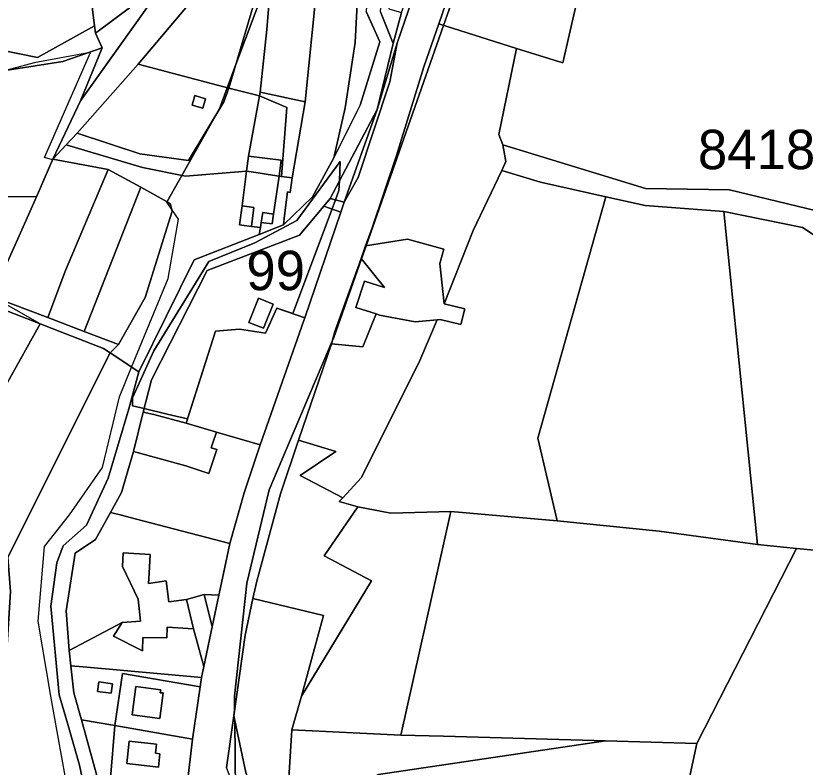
# Model space of a CAD drawing. Extents: x -477304 to -465429, y -1159113 to -1149210.
# Drawn here: x -475584.5 to -475284.1, y -1153027 to -1152741 of the extents above; entities that cross this region are included whole.
import ezdxf

# ---------------------------------------------------------------- set-up
doc = ezdxf.new("R2010")
doc.units = 0
for name, color, linetype in [('BPEJ_s', 7, 'Continuous'), ('orna_s', 7, 'Continuous'), ('ostatni_s', 7, 'Continuous'), ('PUPFL_s', 7, 'Continuous'), ('trav_porost_s', 7, 'Continuous'), ('voda_s', 7, 'Continuous'), ('zahrada_s', 7, 'Continuous')]:
    doc.layers.add(name, color=color, linetype=linetype)

msp = doc.modelspace()

# ---------------------------------------------------------------- linework, layer by layer
at = {"layer": 'BPEJ_s'}
for points in [[(-475500.81, -1153036.32), (-475501.16, -1153009.29), (-475501.54, -1153007.49), (-475501.21, -1153005.16), (-475501.28, -1153000), (-475496.5, -1152957), (-475488, -1152921.5), (-475464.1, -1152864.93), (-475463.5, -1152863.5), (-475452.96, -1152833.54), (-475451.22, -1152828.6), (-475421.69, -1152744.68), (-475407.14, -1152703.33)], [(-475407.14, -1152703.33), (-475421.69, -1152744.68), (-475451.22, -1152828.6), (-475452.96, -1152833.54), (-475463.5, -1152863.5), (-475464.1, -1152864.93), (-475488, -1152921.5), (-475496.5, -1152957), (-475501.28, -1153000), (-475501.21, -1153005.16)], [(-475489.77, -1152730.19), (-475500.69, -1152759.54), (-475504, -1152768.43), (-475507, -1152776.5), (-475507.3, -1152777.03), (-475521.24, -1152801.78), (-475526.88, -1152811.78), (-475527, -1152812), (-475525.07, -1152814.79), (-475524.91, -1152815.39), (-475535.25, -1152848.29), (-475545.44, -1152866.11), (-475548.51, -1152869.36), (-475587.54, -1152947.04)], [(-475563.53, -1153042.27), (-475569, -1153012), (-475571.07, -1153000), (-475576, -1152971.5), (-475573.5, -1152943), (-475564, -1152931), (-475551.5, -1152913), (-475545, -1152886), (-475540.37, -1152874.73), (-475526.5, -1152841), (-475522.5, -1152818.5), (-475525.07, -1152814.79), (-475527, -1152812), (-475526.88, -1152811.78), (-475521.24, -1152801.78), (-475507.3, -1152777.03), (-475507, -1152776.5), (-475504, -1152768.43), (-475500.69, -1152759.54), (-475489.77, -1152730.19)], [(-475619.33, -1152937.28), (-475575.21, -1152858.31), (-475593.59, -1152847.84), (-475576.52, -1152809.97), (-475570.52, -1152795.86), (-475573.5, -1152795), (-475556, -1152755), (-475557.53, -1152755.29), (-475577.5, -1152759), (-475587.33, -1152761.64)], [(-475619.33, -1152937.28), (-475575.21, -1152858.31), (-475593.59, -1152847.84), (-475576.52, -1152809.97), (-475570.52, -1152795.86), (-475573.5, -1152795), (-475556, -1152755), (-475557.53, -1152755.29), (-475577.5, -1152759), (-475587.33, -1152761.64)], [(-475524.91, -1152815.39), (-475535.25, -1152848.29), (-475545.44, -1152866.11), (-475548.51, -1152869.36), (-475587.54, -1152947.04)], [(-475563.53, -1153042.27), (-475569, -1153012), (-475571.07, -1153000), (-475576, -1152971.5), (-475573.5, -1152943), (-475564, -1152931), (-475551.5, -1152913), (-475545, -1152886), (-475540.37, -1152874.73), (-475526.5, -1152841), (-475522.5, -1152818.5), (-475525.07, -1152814.79), (-475524.91, -1152815.39)], [(-475268.28, -1152945.55), (-475287.45, -1152943.72), (-475325.37, -1153017.96), (-475330.61, -1153042.24)], [(-475268.28, -1152945.55), (-475287.45, -1152943.72), (-475325.37, -1153017.96), (-475330.61, -1153042.24)], [(-475501.21, -1153005.16), (-475501.54, -1153007.49), (-475501.16, -1153009.29), (-475500.81, -1153036.32)]]:
    msp.add_lwpolyline(points, dxfattribs=at)
for points in [[(-475464.14, -1152814.54), (-475479.09, -1152854.4), (-475485.14, -1152852.33), (-475489.52, -1152861.83), (-475499.35, -1152860.35), (-475508.44, -1152861.13), (-475519.11, -1152894.42), (-475526.82, -1152892.6), (-475535.6, -1152890.53), (-475540, -1152889.5), (-475540, -1152886.5), (-475532, -1152868.5), (-475511, -1152834.5), (-475493.5, -1152827.5), (-475477.5, -1152819), (-475461, -1152796.5), (-475461.34, -1152803.9), (-475461.5, -1152807.5), (-475462.83, -1152811.05)], [(-475464.14, -1152814.54), (-475462.83, -1152811.05), (-475461.5, -1152807.5), (-475461.34, -1152803.9), (-475461, -1152796.5), (-475477.5, -1152819), (-475493.5, -1152827.5), (-475511, -1152834.5), (-475532, -1152868.5), (-475540, -1152886.5), (-475540, -1152889.5), (-475535.6, -1152890.53), (-475526.82, -1152892.6), (-475519.11, -1152894.42), (-475508.44, -1152861.13), (-475499.35, -1152860.35), (-475489.52, -1152861.83), (-475485.14, -1152852.33), (-475479.09, -1152854.4)]]:
    msp.add_lwpolyline(points, close=True, dxfattribs=at)
at = {"layer": 'orna_s'}
for points in [[(-475474.41, -1152773.74), (-475470.29, -1152733.49), (-475466.26, -1152707.82), (-475459.33, -1152709.97), (-475453.25, -1152709.43), (-475455.35, -1152751.18), (-475459.14, -1152776.1), (-475463.5, -1152795.08), (-475471.52, -1152809.95), (-475482.63, -1152820.63), (-475482.23, -1152817.05), (-475481.05, -1152808.1), (-475480.01, -1152808.24), (-475479.28, -1152802.69)], [(-475492.49, -1152731.72), (-475503.36, -1152768.6), (-475537.87, -1152759.39), (-475508.67, -1152724.8), (-475503.55, -1152727.41)], [(-475488.91, -1152746.29), (-475487.74, -1152730.6), (-475483.62, -1152731.43), (-475470.29, -1152733.49), (-475474.41, -1152773.74), (-475491.45, -1152770.14)], [(-475537.87, -1152759.39), (-475503.36, -1152768.6), (-475505.33, -1152773.76), (-475518.78, -1152796.1), (-475537.26, -1152793.53), (-475561.15, -1152785.65)], [(-475516.28, -1152771.43), (-475517.38, -1152775.02), (-475513.35, -1152776.25), (-475512.25, -1152772.66)], [(-475593.59, -1152847.84), (-475576.52, -1152809.97), (-475570.41, -1152795.61), (-475549.31, -1152799.53), (-475565.52, -1152837.98), (-475572.32, -1152855.91)]]:
    msp.add_lwpolyline(points, close=True, dxfattribs=at)
at = {"layer": 'ostatni_s'}
for points in [[(-475528.22, -1152728.96), (-475516.03, -1152717.12), (-475516.8, -1152709.11), (-475525.94, -1152703.82), (-475549.78, -1152702.51), (-475561.12, -1152693.94), (-475574.39, -1152690.12), (-475584.04, -1152671.96), (-475547.68, -1152668.96), (-475550.48, -1152681.26), (-475495.82, -1152689.6), (-475490.4, -1152697.4), (-475498.36, -1152710.25), (-475510.93, -1152722.23), (-475508.67, -1152724.8), (-475537.87, -1152759.39), (-475561.15, -1152785.65), (-475565.28, -1152790.1), (-475570.41, -1152795.61), (-475559.87, -1152773.35)], [(-475429.06, -1152720.89), (-475430.92, -1152726.59), (-475439.34, -1152751.52), (-475447.03, -1152776.68), (-475440.93, -1152751.63), (-475437.73, -1152739.75), (-475430.58, -1152719.98)], [(-475454.24, -1152802.53), (-475459.54, -1152811.92), (-475447.03, -1152776.68), (-475439.34, -1152751.52), (-475442.11, -1152766.19)], [(-475513.35, -1152776.25), (-475517.38, -1152775.02), (-475516.28, -1152771.43), (-475512.25, -1152772.66)], [(-475464.82, -1152810.53), (-475447.03, -1152776.68), (-475459.54, -1152811.92)], [(-475486.38, -1152816.51), (-475490.52, -1152815.96), (-475491.06, -1152819.68), (-475491.35, -1152821.65), (-475494.81, -1152821.19), (-475493.89, -1152813.96), (-475498.35, -1152813.37), (-475496.67, -1152800.17), (-475492.21, -1152800.76), (-475488.39, -1152801.5), (-475484.25, -1152802.04)], [(-475483.43, -1152802.15), (-475479.28, -1152802.69), (-475480.01, -1152808.24), (-475481.05, -1152808.1), (-475482.23, -1152817.05), (-475482.63, -1152820.63), (-475491.87, -1152824.25), (-475491.35, -1152821.65), (-475491.06, -1152819.68), (-475486.87, -1152820.23), (-475486.38, -1152816.51), (-475484.25, -1152802.04)], [(-475464.82, -1152810.53), (-475459.54, -1152811.92), (-475460.83, -1152815.72), (-475467.24, -1152813.44)], [(-475499.35, -1152860.35), (-475508.44, -1152861.13), (-475519.66, -1152896.13), (-475531.89, -1152892.84), (-475535.95, -1152891.92), (-475532.87, -1152879.56), (-475511.67, -1152838.03), (-475476.52, -1152824.58), (-475467.24, -1152813.44), (-475460.83, -1152815.72), (-475474.51, -1152855.97), (-475485.14, -1152852.33), (-475489.52, -1152861.83)], [(-475499.35, -1152820.59), (-475498.35, -1152813.37), (-475493.89, -1152813.96), (-475494.81, -1152821.19)], [(-475490.52, -1152815.96), (-475486.38, -1152816.51), (-475486.87, -1152820.23), (-475491.06, -1152819.68)], [(-475435.38, -1152826.04), (-475421.65, -1152829.81), (-475423.16, -1152835.29), (-475421.55, -1152850.68), (-475413.67, -1152852.57), (-475415.09, -1152858.5), (-475422.97, -1152856.61), (-475424.14, -1152856.73), (-475432.48, -1152857.55), (-475446.06, -1152854.94), (-475447.4, -1152854.49), (-475455.03, -1152852.06), (-475451.82, -1152842.06), (-475444.2, -1152844.51), (-475453.09, -1152833.38), (-475451.39, -1152828.63)], [(-475490.22, -1152859.94), (-475486.59, -1152850.73), (-475492.17, -1152848.53), (-475495.8, -1152857.74)], [(-475486.59, -1152850.73), (-475490.22, -1152859.94), (-475495.8, -1152857.74), (-475492.17, -1152848.53)], [(-475509.64, -1152903.9), (-475510.15, -1152905.42), (-475507.97, -1152906.15), (-475511.03, -1152915.25), (-475519.75, -1152912.32), (-475539.67, -1152906.85), (-475535.95, -1152891.92), (-475531.89, -1152892.84), (-475519.66, -1152896.13), (-475508.15, -1152899.46)], [(-475533.29, -1152946.04), (-475543.57, -1152945.42), (-475543.89, -1152950.61), (-475537.86, -1152963.03), (-475537.03, -1152971.49), (-475544.04, -1152971.94), (-475564.12, -1152982.64), (-475565.3, -1152967.49), (-475561.8, -1152945.58), (-475554.15, -1152940.37), (-475548.43, -1152930.05), (-475544.24, -1152931.13), (-475538.99, -1152932.46), (-475503.01, -1152941.9), (-475505.46, -1152953.31), (-475507.18, -1152961.51), (-475512.75, -1152961.31), (-475519.5, -1152963.16), (-475526.22, -1152964.09), (-475527.23, -1152956.14), (-475533.95, -1152957.07), (-475533.72, -1152953.13)], [(-475533.95, -1152957.07), (-475527.23, -1152956.14), (-475526.22, -1152964.09), (-475519.5, -1152963.16), (-475516.91, -1152974.32), (-475526.88, -1152973.78), (-475526.96, -1152977.78), (-475536.06, -1152977.6), (-475536.23, -1152982.69), (-475547.34, -1152977.21), (-475544.04, -1152971.94), (-475537.03, -1152971.49), (-475537.86, -1152963.03), (-475543.89, -1152950.61), (-475543.57, -1152945.42), (-475533.29, -1152946.04), (-475533.72, -1152953.13)], [(-475516.91, -1152974.32), (-475519.5, -1152963.16), (-475512.75, -1152961.31), (-475509.71, -1152973.57), (-475512.88, -1152988.66)], [(-475546.78, -1153011.14), (-475543.84, -1152991.36), (-475514.34, -1152996.46), (-475517.23, -1153016.33)], [(-475553.36, -1152998.26), (-475552.92, -1152994.58), (-475547.7, -1152995.24), (-475548.15, -1152998.9)], [(-475538.76, -1152996.3), (-475540.14, -1153007.12), (-475529.68, -1153008.45), (-475528.44, -1152998.75), (-475529.47, -1152998.7), (-475529.32, -1152997.51)], [(-475529.47, -1152998.7), (-475528.44, -1152998.75), (-475529.68, -1153008.45), (-475540.14, -1153007.12), (-475538.76, -1152996.3), (-475529.32, -1152997.51)], [(-475471.51, -1153122.26), (-475483.51, -1153143.2), (-475484.05, -1153148.63), (-475463.25, -1153144.42), (-475478.77, -1153148.77), (-475489.43, -1153151.64), (-475491.02, -1153144.27), (-475478.7, -1153120.92), (-475475.62, -1153106.62), (-475482.9, -1153085.35), (-475494.64, -1153052.66), (-475504.3, -1153027.08), (-475501.54, -1153007.49), (-475496.95, -1153029.07), (-475472.52, -1153095.04), (-475474.55, -1153095.68), (-475469.57, -1153111.41)], [(-475546.78, -1153011.14), (-475517.23, -1153016.33), (-475519.45, -1153035.84), (-475548.45, -1153031.15)], [(-475530.21, -1153026.97), (-475529.67, -1153021.91), (-475531.35, -1153021.73), (-475530.98, -1153018.27), (-475541.35, -1153017.16), (-475542.27, -1153025.67)], [(-475530.21, -1153026.97), (-475542.27, -1153025.67), (-475541.35, -1153017.16), (-475530.98, -1153018.27), (-475531.35, -1153021.73), (-475529.67, -1153021.91)]]:
    msp.add_lwpolyline(points, close=True, dxfattribs=at)
for points in [[(-475412.15, -1152710.92), (-475423.54, -1152744.1), (-475429.17, -1152760.48), (-475439.62, -1152794.25), (-475448.91, -1152821.68), (-475451.39, -1152828.63), (-475453.09, -1152833.38), (-475463.02, -1152861.18), (-475464.37, -1152865.85), (-475476.85, -1152902.59), (-475483.8, -1152923.03), (-475492.8, -1152956.23), (-475494.22, -1152962.84), (-475497.2, -1152976.78), (-475501.54, -1153007.49), (-475504.3, -1153027.08)], [(-475510.82, -1153134.41), (-475513.74, -1153112.64), (-475517.49, -1153089), (-475520.57, -1153045.64), (-475519.45, -1153035.84), (-475517.23, -1153016.33), (-475514.34, -1152996.46), (-475513.77, -1152992.91), (-475512.88, -1152988.66), (-475509.71, -1152973.57), (-475507.18, -1152961.51), (-475505.46, -1152953.31), (-475503.01, -1152941.9), (-475497.54, -1152922.65), (-475491.51, -1152904.28), (-475474.88, -1152857.07), (-475474.51, -1152855.97), (-475460.83, -1152815.72), (-475459.54, -1152811.92), (-475454.24, -1152802.53), (-475442.11, -1152766.19), (-475439.34, -1152751.52), (-475430.92, -1152726.59)], [(-475593.59, -1152847.84), (-475572.32, -1152855.91), (-475558.47, -1152861.17), (-475545.44, -1152866.11), (-475535.25, -1152848.29), (-475524.91, -1152815.39), (-475525.7, -1152812.42), (-475536.93, -1152806.29), (-475549.31, -1152799.53), (-475570.41, -1152795.61), (-475565.28, -1152790.1), (-475536.3, -1152798.75), (-475519.91, -1152802.05), (-475496.67, -1152800.17), (-475498.35, -1152813.37), (-475499.35, -1152820.59), (-475494.81, -1152821.19), (-475491.35, -1152821.65), (-475491.87, -1152824.25), (-475516.59, -1152833.94), (-475537.64, -1152876.53), (-475548.51, -1152869.36), (-475551.06, -1152867.68), (-475575.21, -1152858.31), (-475594.83, -1152850.7)]]:
    msp.add_lwpolyline(points, dxfattribs=at)
at = {"layer": 'PUPFL_s'}
for points in [[(-475688.75, -1152784.73), (-475693.19, -1152770.91), (-475686.56, -1152768.49), (-475621.57, -1152758.65), (-475624.23, -1152747.16), (-475576.16, -1152756.87), (-475554.46, -1152744.91), (-475554.12, -1152747.68), (-475551.6, -1152753.22), (-475566.51, -1152758.41), (-475598.28, -1152763.34), (-475604.67, -1152767.58), (-475593.82, -1152785.42), (-475688.69, -1152799.79)], [(-475694.55, -1152800.67), (-475688.69, -1152799.79), (-475593.82, -1152785.42), (-475604.67, -1152767.58), (-475598.28, -1152763.34), (-475566.51, -1152758.41), (-475551.6, -1152753.22), (-475559.87, -1152773.35), (-475570.41, -1152795.61), (-475576.52, -1152809.97), (-475644.5, -1152809.53), (-475700.83, -1152807.76), (-475694.32, -1152806.09)], [(-475154.57, -1152960.71), (-475188.25, -1153073.92), (-475205.9, -1153072.04), (-475319.2, -1153107.9), (-475350.51, -1153121.3), (-475347.24, -1153109.36), (-475336.52, -1153070.18), (-475330.61, -1153042.24), (-475325.37, -1153017.96), (-475287.45, -1152943.72), (-475268.28, -1152945.55), (-475240.48, -1152947.68), (-475185.82, -1152950.28), (-475184.7, -1152902.6), (-475190.97, -1152854.13), (-475193.07, -1152845.82), (-475161.18, -1152813.24), (-475126.45, -1152850.38), (-475138.02, -1152881.46), (-475143.48, -1152923), (-475153.28, -1152956.92)], [(-475575.21, -1152858.31), (-475619.33, -1152937.28), (-475611.96, -1152940.26), (-475621.62, -1152973.88), (-475613.73, -1152977.13), (-475617.49, -1153013.79), (-475630.92, -1152974.27), (-475631.11, -1153024.55), (-475648.02, -1153026.57), (-475643.82, -1153008.41), (-475642.55, -1152978.65), (-475635.17, -1152947.89), (-475627.73, -1152930.46), (-475594.83, -1152850.7)]]:
    msp.add_lwpolyline(points, close=True, dxfattribs=at)
for points in [[(-475743.28, -1152815.41), (-475700.83, -1152807.76), (-475644.5, -1152809.53), (-475576.52, -1152809.97), (-475593.59, -1152847.84), (-475594.83, -1152850.7), (-475627.73, -1152930.46), (-475635.17, -1152947.89), (-475642.55, -1152978.65), (-475643.82, -1153008.41), (-475648.02, -1153026.57), (-475631.11, -1153024.55), (-475635.36, -1153085.02), (-475662.21, -1153095.67), (-475701.5, -1153108.22), (-475770.43, -1153174.06)], [(-475635.36, -1153085.02), (-475631.11, -1153024.55), (-475630.92, -1152974.27), (-475617.49, -1153013.79), (-475590.2, -1153019.39), (-475586.48, -1152960.09), (-475587.54, -1152947.04), (-475548.51, -1152869.36), (-475537.64, -1152876.53), (-475541.47, -1152890.66), (-475549.36, -1152917.02), (-475557.61, -1152934.96), (-475566.47, -1152942.81), (-475568.81, -1152949.28), (-475571.1, -1152965.73), (-475567.92, -1152999.53), (-475564.76, -1153010.23), (-475560.24, -1153026.23), (-475557.79, -1153037.72)]]:
    msp.add_lwpolyline(points, dxfattribs=at)
at = {"layer": 'trav_porost_s'}
for points in [[(-475563.59, -1152714.27), (-475556.79, -1152726.11), (-475554.46, -1152744.91), (-475576.16, -1152756.87), (-475624.23, -1152747.16), (-475621.57, -1152758.65), (-475686.56, -1152768.49), (-475695.79, -1152741.11), (-475675.66, -1152712.58), (-475642.36, -1152708.05), (-475639.99, -1152696.96), (-475614.53, -1152691.15), (-475585.75, -1152697.58), (-475579.41, -1152701.49), (-475568.62, -1152709.29)], [(-475556.79, -1152726.11), (-475563.59, -1152714.27), (-475568.62, -1152709.29), (-475579.41, -1152701.49), (-475574.39, -1152690.12), (-475561.12, -1152693.94), (-475549.78, -1152702.51), (-475547.62, -1152704.31), (-475539.13, -1152723.9), (-475540.16, -1152737.25), (-475554.12, -1152747.68), (-475554.46, -1152744.91)], [(-475554.12, -1152747.68), (-475540.16, -1152737.25), (-475539.13, -1152723.9), (-475547.62, -1152704.31), (-475549.78, -1152702.51), (-475525.94, -1152703.82), (-475516.8, -1152709.11), (-475516.03, -1152717.12), (-475528.22, -1152728.96), (-475559.87, -1152773.35), (-475551.6, -1152753.22)], [(-475393.95, -1152753.43), (-475423.54, -1152744.1), (-475412.15, -1152710.92), (-475408.98, -1152702.9), (-475391.14, -1152707.11), (-475386.32, -1152711.18), (-475378.53, -1152710.47), (-475366.01, -1152713.43), (-475376.34, -1152758.98)], [(-475451.16, -1152739.41), (-475446.01, -1152751.01), (-475453.49, -1152775), (-475463.5, -1152795.08), (-475459.14, -1152776.1), (-475455.35, -1152751.18), (-475453.25, -1152709.43), (-475449.1, -1152710.68)], [(-475279.36, -1152735.39), (-475267.5, -1152741.66), (-475238.97, -1152771.86), (-475246.77, -1152833.38), (-475279.83, -1152815.27), (-475312.9, -1152807.3), (-475344.92, -1152806.82), (-475399.13, -1152790.1), (-475400.75, -1152786.24), (-475393.95, -1152753.43), (-475376.34, -1152758.98), (-475366.01, -1152713.43), (-475311.18, -1152726.4), (-475305.99, -1152727.63)], [(-475492.49, -1152731.72), (-475503.55, -1152727.41), (-475487.74, -1152730.6), (-475488.91, -1152746.29), (-475491.45, -1152770.14), (-475491.69, -1152771.47), (-475503.36, -1152768.6)], [(-475400.75, -1152786.24), (-475399.13, -1152790.1), (-475397.98, -1152796.54), (-475399.54, -1152799.89), (-475410.48, -1152822.74), (-475421.55, -1152850.68), (-475423.16, -1152835.29), (-475421.65, -1152829.81), (-475435.38, -1152826.04), (-475451.39, -1152828.63), (-475448.91, -1152821.68), (-475439.62, -1152794.25), (-475429.17, -1152760.48), (-475423.54, -1152744.1), (-475393.95, -1152753.43)], [(-475519.91, -1152802.05), (-475536.3, -1152798.75), (-475565.28, -1152790.1), (-475561.15, -1152785.65), (-475537.26, -1152793.53), (-475518.78, -1152796.1), (-475505.33, -1152773.76), (-475503.36, -1152768.6), (-475491.69, -1152771.47), (-475495.93, -1152794.52), (-475496.67, -1152800.17)], [(-475491.45, -1152770.14), (-475474.41, -1152773.74), (-475479.28, -1152802.69), (-475483.43, -1152802.15), (-475481.32, -1152775.88), (-475491.69, -1152771.47)], [(-475495.93, -1152794.52), (-475491.69, -1152771.47), (-475481.32, -1152775.88), (-475483.43, -1152802.15), (-475484.25, -1152802.04), (-475483.45, -1152795.99)], [(-475384.78, -1152804.32), (-475399.54, -1152799.89), (-475397.98, -1152796.54), (-475399.13, -1152790.1), (-475344.92, -1152806.82), (-475312.9, -1152807.3), (-475279.83, -1152815.27), (-475246.77, -1152833.38), (-475201.18, -1152853.32), (-475240.42, -1152843.05), (-475262.43, -1152836.75), (-475285.2, -1152821.61), (-475315.16, -1152815.54), (-475345, -1152813.24), (-475359.94, -1152810)], [(-475484.25, -1152802.04), (-475488.39, -1152801.5), (-475492.21, -1152800.76), (-475496.67, -1152800.17), (-475495.93, -1152794.52), (-475483.45, -1152795.99)], [(-475558.47, -1152861.17), (-475572.32, -1152855.91), (-475565.52, -1152837.98), (-475549.31, -1152799.53), (-475536.93, -1152806.29)], [(-475460.02, -1152924.47), (-475452.88, -1152916.76), (-475430.76, -1152872.18), (-475424.14, -1152856.73), (-475422.97, -1152856.61), (-475415.09, -1152858.5), (-475413.67, -1152852.57), (-475421.55, -1152850.68), (-475410.48, -1152822.74), (-475399.54, -1152799.89), (-475384.78, -1152804.32), (-475359.94, -1152810), (-475385.91, -1152901.78), (-475378.54, -1152933.24), (-475418.96, -1152929.67), (-475441.84, -1152930.38), (-475454.37, -1152927.96), (-475461.39, -1152925.95)], [(-475525.7, -1152812.42), (-475524.91, -1152815.39), (-475535.25, -1152848.29), (-475545.44, -1152866.11), (-475558.47, -1152861.17), (-475536.93, -1152806.29)], [(-475385.91, -1152901.78), (-475359.94, -1152810), (-475345, -1152813.24), (-475315.16, -1152815.54), (-475302.24, -1152942.31), (-475339.72, -1152937.13), (-475378.54, -1152933.24)], [(-475268.28, -1152945.55), (-475287.45, -1152943.72), (-475302.24, -1152942.31), (-475315.16, -1152815.54), (-475285.2, -1152821.61), (-475262.43, -1152836.75), (-475240.42, -1152843.05), (-475244.73, -1152856.39), (-475221.7, -1152869.94), (-475234.99, -1152909.87), (-475240.48, -1152947.68)], [(-475485.14, -1152852.33), (-475474.51, -1152855.97), (-475474.88, -1152857.07), (-475491.51, -1152904.28), (-475508.15, -1152899.46), (-475519.66, -1152896.13), (-475508.44, -1152861.13), (-475499.35, -1152860.35), (-475489.52, -1152861.83)], [(-475548.51, -1152869.36), (-475587.54, -1152947.04), (-475586.48, -1152960.09), (-475590.2, -1153019.39), (-475617.49, -1153013.79), (-475613.73, -1152977.13), (-475621.62, -1152973.88), (-475611.96, -1152940.26), (-475619.33, -1152937.28), (-475575.21, -1152858.31), (-475551.06, -1152867.68)], [(-475483.8, -1152923.03), (-475476.85, -1152902.59), (-475462.75, -1152906.9), (-475476.32, -1152916.03), (-475460.02, -1152924.47), (-475461.39, -1152925.95), (-475454.37, -1152927.96), (-475467.1, -1152946.61), (-475449.11, -1152956.13), (-475475.8, -1153000), (-475467.4, -1152969.33), (-475494.22, -1152962.84), (-475492.8, -1152956.23)], [(-475449.11, -1152956.13), (-475467.1, -1152946.61), (-475454.37, -1152927.96), (-475441.84, -1152930.38), (-475418.96, -1152929.67), (-475437.91, -1153014.81), (-475479.39, -1153012.83), (-475475.8, -1153000)], [(-475302.24, -1152942.31), (-475287.45, -1152943.72), (-475325.37, -1153017.96), (-475360.14, -1153016.97), (-475421.68, -1153015.23), (-475437.91, -1153014.81), (-475418.96, -1152929.67), (-475378.54, -1152933.24), (-475339.72, -1152937.13)], [(-475512.75, -1152961.31), (-475507.18, -1152961.51), (-475509.71, -1152973.57)], [(-475494.22, -1152962.84), (-475467.4, -1152969.33), (-475475.8, -1153000), (-475479.39, -1153012.83), (-475481.6, -1153047.42), (-475463.12, -1153092.06), (-475466.61, -1153093.16), (-475472.52, -1153095.04), (-475496.95, -1153029.07), (-475501.54, -1153007.49), (-475497.2, -1152976.78)], [(-475526.88, -1152973.78), (-475516.91, -1152974.32), (-475512.88, -1152988.66), (-475513.77, -1152992.91), (-475558.81, -1152988.85), (-475563.49, -1152988.42), (-475564.12, -1152982.64), (-475544.04, -1152971.94), (-475547.34, -1152977.21), (-475536.23, -1152982.69), (-475536.06, -1152977.6), (-475526.96, -1152977.78)], [(-475563.49, -1152988.42), (-475558.81, -1152988.85), (-475513.77, -1152992.91), (-475514.34, -1152996.46), (-475543.84, -1152991.36), (-475546.78, -1153011.14), (-475559.5, -1153009.05), (-475562.37, -1152998.73)], [(-475553.36, -1152998.26), (-475548.15, -1152998.9), (-475547.7, -1152995.24), (-475552.92, -1152994.58)], [(-475559.5, -1153009.05), (-475546.78, -1153011.14), (-475548.45, -1153031.15), (-475553.48, -1153030.67)], [(-475437.91, -1153014.81), (-475421.68, -1153015.23), (-475360.14, -1153016.97), (-475446.53, -1153029.81), (-475481.6, -1153047.42), (-475479.39, -1153012.83)], [(-475463.12, -1153092.06), (-475481.6, -1153047.42), (-475446.53, -1153029.81), (-475360.14, -1153016.97), (-475325.37, -1153017.96), (-475330.61, -1153042.24), (-475336.52, -1153070.18), (-475462.34, -1153123.43), (-475461.63, -1153108.89), (-475461.12, -1153095.55)]]:
    msp.add_lwpolyline(points, close=True, dxfattribs=at)
at = {"layer": 'voda_s'}
for points in [[(-475557.79, -1153037.72), (-475560.24, -1153026.23), (-475564.76, -1153010.23), (-475567.92, -1152999.53), (-475571.1, -1152965.73), (-475568.81, -1152949.28), (-475566.47, -1152942.81), (-475557.61, -1152934.96), (-475549.36, -1152917.02), (-475541.47, -1152890.66), (-475537.64, -1152876.53), (-475516.59, -1152833.94), (-475491.87, -1152824.25), (-475482.63, -1152820.63), (-475471.52, -1152809.95), (-475463.5, -1152795.08), (-475453.49, -1152775), (-475446.01, -1152751.01), (-475451.16, -1152739.41)], [(-475445.76, -1152739.47), (-475440.93, -1152751.63), (-475447.03, -1152776.68), (-475464.82, -1152810.53), (-475467.24, -1152813.44), (-475476.52, -1152824.58), (-475511.67, -1152838.03), (-475532.87, -1152879.56), (-475535.95, -1152891.92), (-475539.67, -1152906.85), (-475544.24, -1152922.49), (-475548.43, -1152930.05), (-475554.15, -1152940.37), (-475561.8, -1152945.58), (-475565.3, -1152967.49), (-475564.12, -1152982.64), (-475563.49, -1152988.42), (-475562.37, -1152998.73), (-475559.5, -1153009.05), (-475553.48, -1153030.67)]]:
    msp.add_lwpolyline(points, dxfattribs=at)
at = {"layer": 'zahrada_s'}
for points in [[(-475439.25, -1152725.01), (-475442.55, -1152738.35), (-475437.73, -1152739.75), (-475440.93, -1152751.63), (-475445.76, -1152739.47), (-475443.64, -1152712.13), (-475438.91, -1152714.97)], [(-475464.37, -1152865.85), (-475463.02, -1152861.18), (-475453.09, -1152833.38), (-475444.2, -1152844.51), (-475451.82, -1152842.06), (-475455.03, -1152852.06), (-475447.4, -1152854.49), (-475452.4, -1152867.04)], [(-475430.76, -1152872.18), (-475452.88, -1152916.76), (-475460.02, -1152924.47), (-475476.32, -1152916.03), (-475462.75, -1152906.9), (-475476.85, -1152902.59), (-475464.37, -1152865.85), (-475452.4, -1152867.04), (-475447.4, -1152854.49), (-475446.06, -1152854.94), (-475432.48, -1152857.55), (-475424.14, -1152856.73)], [(-475538.99, -1152932.46), (-475544.24, -1152931.13), (-475548.43, -1152930.05), (-475544.24, -1152922.49), (-475539.67, -1152906.85), (-475519.75, -1152912.32), (-475511.03, -1152915.25), (-475507.97, -1152906.15), (-475510.15, -1152905.42), (-475509.64, -1152903.9), (-475508.15, -1152899.46), (-475491.51, -1152904.28), (-475497.54, -1152922.65), (-475503.01, -1152941.9)]]:
    msp.add_lwpolyline(points, close=True, dxfattribs=at)

# ---------------------------------------------------------------- texts
at = {"layer": 'BPEJ_s'}
for s, p in [('84189/V.', (-475324.96, -1152799.41)), ('99', (-475496.75, -1152845.46))]:
    msp.add_text(s, height=15, dxfattribs=at).set_placement(p)

doc.saveas('drawing.dxf')
